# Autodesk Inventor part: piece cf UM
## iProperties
Shininess: 20.0
Length Units: 11269
Angle Units: 11279
Time Units: 11290
Mass Units: 11283
Length Display Precision: 3
Angle Display Precision: 2
Created: 2001-04
Part Number: piece cf UM
Material: Par défaut
Document SubType Name: Modélisation
Designer: jost
Density: 0.0
Volumn: 0.0
Area: 0.0
PropertySet Name: Model Information
Control State: 0
Master: False
Checked Out: False
Author: jost
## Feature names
1. Extrusion1
2. Extrusion2
